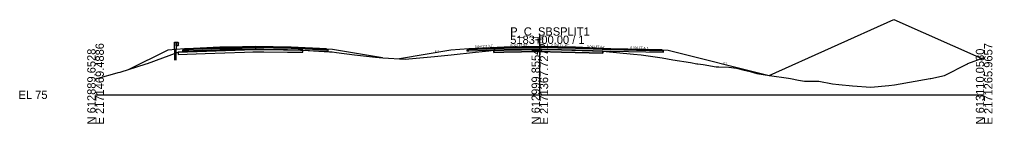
# Model space of a CAD drawing. Extents: x -26 to 1303, y -3010 to 12033.
# Drawn here: x -25.7 to 302.8, y 5990.3 to 6025.5 of the extents above; entities that cross this region are included whole.
import ezdxf

# ---------------------------------------------------------------- set-up
doc = ezdxf.new("R2010")
doc.units = 0
for name, color, linetype in [('RD_GPK_XS_Cell', 7, 'Continuous'), ('RD_PD_Final_TrvlWay', 7, 'Continuous'), ('RD_Sketch10', 7, 'Continuous'), ('RD_XS_Base', 7, 'Continuous'), ('RD_XS_ExGround', 7, 'Continuous'), ('RD_XS_ExPaveRet', 7, 'Continuous'), ('RD_XS_GR', 7, 'Continuous'), ('RD_XS_Greenside', 7, 'Continuous'), ('RD_XS_Pave', 7, 'Continuous'), ('RD_XS_PaveOvlay_CP', 7, 'Continuous'), ('RD_XS_TieSlope', 7, 'Continuous'), ('RD_XS_TX_Elev_EX', 7, 'Continuous'), ('RD_XS_TX_Elev_PR', 7, 'Continuous'), ('RD_XS_TX_Slope', 7, 'Continuous')]:
    doc.layers.add(name, color=color, linetype=linetype)

msp = doc.modelspace()

# ---------------------------------------------------------------- linework, layer by layer
at = {"layer": 'RD_GPK_XS_Cell'}
for p, q in [((150, 6000), (150, 6020)), ((0, 6000), (150, 6000)), ((150, 6000), (300, 6000))]:
    msp.add_line(p, q, dxfattribs=at)
at = {"layer": 'RD_PD_Final_TrvlWay'}
msp.add_lwpolyline([(27.17, 6011.74), (27.17, 6015.35), (26.67, 6015.31), (26.67, 6011.74)], dxfattribs=at)
at = {"layer": 'RD_Sketch10'}
msp.add_lwpolyline([(227.42, 6006.55), (269.55, 6025.46), (299.19, 6012.32)], dxfattribs=at)
at = {"layer": 'RD_XS_Base'}
for p, q in [((33.12, 6015.38), (42, 6015.73)), ((42, 6015.73), (45.12, 6015.8)), ((45.12, 6015.8), (54, 6015.97)), ((54, 6015.47), (45.12, 6015.3)), ((54, 6016.01), (54, 6016.13)), ((54, 6016.13), (54, 6015.64)), ((54, 6015.97), (54, 6016.13)), ((54, 6016.13), (54, 6015.47)), ((54, 6015.97), (54, 6016.01)), ((54, 6015.97), (54, 6015.6)), ((54, 6015.97), (54, 6015.47)), ((66, 6015.73), (54, 6015.97)), ((54, 6015.97), (54, 6015.97)), ((54, 6015.64), (54, 6015.47)), ((54, 6015.6), (54, 6015.47)), ((54, 6015.47), (54, 6015.47)), ((54, 6015.47), (54, 6015.47)), ((54, 6015.47), (66, 6015.23)), ((78, 6015.25), (66, 6015.73)), ((68, 6015.65), (68, 6015.65)), ((126, 6015.26), (138, 6015.74)), ((138, 6015.74), (150, 6015.98)), ((150, 6015.48), (138, 6015.24)), ((150, 6015.98), (150, 6016.14)), ((150, 6016.14), (150, 6015.48)), ((150, 6015.98), (150, 6015.98)), ((162, 6015.74), (150, 6015.98)), ((150, 6015.98), (150, 6015.98)), ((150, 6015.98), (150, 6015.48)), ((150, 6015.48), (150, 6015.48)), ((150, 6015.48), (162, 6015.24)), ((150, 6015.48), (150, 6015.48)), ((174, 6015.26), (162, 6015.74)), ((162, 6015.74), (162, 6015.74)), ((29.5, 6015.23), (29.63, 6015.24)), ((29.5, 6014.86), (29.5, 6015.23)), ((29.5, 6014.73), (29.5, 6014.86)), ((29.63, 6014.74), (29.5, 6014.73)), ((29.63, 6015.24), (30, 6015.25)), ((30, 6014.75), (29.63, 6014.74)), ((30, 6015.25), (33.12, 6015.38)), ((33.12, 6014.88), (30, 6014.75)), ((42, 6015.23), (33.12, 6014.88)), ((45.12, 6015.3), (42, 6015.23)), ((66, 6015.23), (78.5, 6014.73)), ((68, 6015.15), (68, 6015.15)), ((78.5, 6015.23), (78, 6015.25)), ((78, 6015.25), (78, 6015.25)), ((78.5, 6014.73), (78.5, 6015.23)), ((78.5, 6015.23), (78.5, 6015.23)), ((78.5, 6014.73), (78.5, 6014.73)), ((78.5, 6014.73), (78.5, 6014.73)), ((125.5, 6015.24), (126, 6015.26)), ((125.5, 6014.74), (125.5, 6015.24)), ((125.5, 6015.24), (125.5, 6015.24)), ((126, 6014.76), (125.5, 6014.74)), ((125.5, 6014.74), (125.5, 6014.74)), ((125.5, 6014.74), (125.5, 6014.74)), ((126, 6015.26), (126, 6015.26)), ((138, 6015.24), (126, 6014.76)), ((126, 6014.76), (126, 6014.76)), ((162, 6015.24), (162, 6015.24)), ((162, 6015.24), (174, 6014.76)), ((191.3, 6014.92), (174, 6015.26)), ((174, 6015.26), (174, 6015.26)), ((174, 6014.76), (174, 6014.76)), ((174, 6014.76), (191.8, 6014.41)), ((191.8, 6014.91), (191.3, 6014.92)), ((191.3, 6014.92), (191.3, 6014.92)), ((191.8, 6014.41), (191.8, 6014.91)), ((191.8, 6014.91), (191.8, 6014.91)), ((191.8, 6014.41), (191.8, 6014.41)), ((191.8, 6014.41), (191.8, 6014.41))]:
    msp.add_line(p, q, dxfattribs=at)
at = {"layer": 'RD_XS_ExGround'}
msp.add_lwpolyline([(0, 6005.43), (0.84, 6005.69), (7.25, 6007.44), (7.67, 6007.53), (8.33, 6007.71), (17.14, 6010.43), (17.59, 6010.61), (22.72, 6012.45), (27.85, 6014.42), (50.25, 6015.17), (54.03, 6015.3), (56.79, 6015.27), (70.03, 6015.13), (79.03, 6014.55), (79.85, 6014.51), (81.31, 6014.33), (87.43, 6013.5), (94.52, 6012.73), (97.02, 6012.53), (104.5, 6012.1), (114.43, 6012.99), (120.1, 6013.49), (128.31, 6014.37), (131.7, 6014.75), (132.73, 6014.86), (134.48, 6015.04), (137.87, 6015.11), (149.77, 6015.35), (157.32, 6015.15), (171.23, 6014.8), (181.6, 6013.75), (184.21, 6013.5), (186.55, 6013.2), (191.34, 6012.52), (194.86, 6011.87), (200.89, 6010.87), (203.05, 6010.5), (203.39, 6010.48), (205.18, 6010.22), (209.48, 6009.49), (210.47, 6009.51), (213.76, 6009.39), (216.44, 6008.96), (218.99, 6008.34), (221.01, 6007.83), (223.23, 6007.24), (227.59, 6006.52), (233.9, 6005.6), (234.6, 6005.5), (237.37, 6004.99), (239.33, 6004.67), (239.91, 6004.57), (244.24, 6004.57), (248.78, 6003.74), (250.93, 6003.47), (255.6, 6003.04), (261.73, 6002.64), (267.79, 6003.2), (269.73, 6003.37), (281.77, 6005.5), (282.04, 6005.55), (286.67, 6006.49), (294.15, 6010.35), (294.47, 6010.5), (294.55, 6010.54), (300, 6012.63)], dxfattribs=at)
at = {"layer": 'RD_XS_ExPaveRet'}
for points in [[(56.79, 6015.27), (54.7, 6015.3), (54.03, 6015.3), (53.12, 6015.27), (50.25, 6015.17), (36.98, 6014.73), (27.85, 6014.42), (27.85, 6014.42), (27.85, 6014.42), (27.85, 6014.01), (27.85, 6013.67), (27.85, 6013.67), (27.85, 6013.67), (36.98, 6013.98), (50.25, 6014.42), (53.12, 6014.52), (54.03, 6014.55), (54.7, 6014.55), (56.79, 6014.52), (64.8, 6014.43), (70.03, 6014.38), (70.03, 6014.72), (70.03, 6015.13), (64.8, 6015.18), (56.79, 6015.27)], [(56.79, 6015.27), (54.7, 6015.3), (54.03, 6015.3), (53.12, 6015.27), (50.25, 6015.17), (36.98, 6014.73), (27.85, 6014.42), (27.85, 6014.42), (27.85, 6014.42), (27.85, 6014.01), (27.85, 6013.67), (27.85, 6013.67), (27.85, 6013.67), (36.98, 6013.98), (50.25, 6014.42), (53.12, 6014.52), (54.03, 6014.55), (54.7, 6014.55), (56.79, 6014.52), (64.8, 6014.43), (70.03, 6014.38), (70.03, 6014.72), (70.03, 6015.13), (64.8, 6015.18), (56.79, 6015.27)], [(171.23, 6014.8), (171.23, 6014.8), (171.23, 6014.05), (171.23, 6014.05), (157.32, 6014.4), (157.32, 6014.4), (149.77, 6014.6), (149.77, 6014.6), (137.87, 6014.36), (137.87, 6014.36), (134.48, 6014.29), (134.48, 6014.29), (134.48, 6015.04), (134.48, 6015.04), (134.48, 6015.04), (137.87, 6015.11), (137.87, 6015.11), (149.77, 6015.35), (149.77, 6015.35), (157.32, 6015.15), (157.32, 6015.15), (171.23, 6014.8), (171.23, 6014.8)], [(157.32, 6015.15), (149.77, 6015.35), (137.87, 6015.11), (134.48, 6015.04), (134.48, 6014.29), (137.87, 6014.36), (149.77, 6014.6), (157.32, 6014.4), (171.23, 6014.05), (171.23, 6014.8), (157.32, 6015.15)]]:
    msp.add_lwpolyline(points, dxfattribs=at)
at = {"layer": 'RD_XS_GR'}
for p, q in [((26.67, 6015.31), (26.67, 6017.74)), ((26.67, 6017.74), (26.92, 6017.74)), ((26.92, 6017.74), (27.17, 6017.74)), ((27.17, 6017.74), (27.17, 6015.35)), ((27.17, 6016.57), (27.17, 6017.74)), ((27.17, 6017.74), (27.83, 6017.74)), ((27.83, 6016.57), (27.17, 6016.57)), ((27.83, 6017.74), (27.83, 6016.57)), ((28.03, 6017.52), (27.83, 6017.74)), ((27.83, 6017.74), (27.83, 6016.88)), ((27.83, 6017.16), (27.9, 6017.23)), ((28.03, 6016.94), (27.83, 6017.16)), ((27.83, 6016.88), (27.83, 6016.57)), ((27.83, 6016.57), (27.9, 6016.65)), ((27.9, 6017.23), (28.1, 6017.45)), ((27.9, 6016.65), (28.1, 6016.86)), ((28.1, 6017.45), (28.03, 6017.52)), ((28.1, 6016.86), (28.03, 6016.94)), ((27.17, 6015.35), (26.67, 6015.31))]:
    msp.add_line(p, q, dxfattribs=at)
at = {"layer": 'RD_XS_Greenside'}
for p, q in [((24.35, 6015.12), (11.04, 6008.46)), ((80, 6015.41), (96.83, 6012.61)), ((120, 6015.1), (102.63, 6012.21)), ((193.3, 6015.08), (227.42, 6006.55))]:
    msp.add_line(p, q, dxfattribs=at)
at = {"layer": 'RD_XS_Pave'}
for p, q in [((33.12, 6015.7), (30, 6015.57)), ((30, 6015.57), (30, 6015.45)), ((33.12, 6015.54), (30, 6015.41)), ((30, 6015.41), (33.12, 6015.54)), ((30, 6015.45), (30, 6015.41)), ((42, 6016.05), (33.12, 6015.7)), ((42, 6015.89), (33.12, 6015.54)), ((33.12, 6015.54), (42, 6015.89)), ((33.12, 6015.38), (42, 6015.73)), ((45.12, 6016.11), (42, 6016.05)), ((45.12, 6015.95), (42, 6015.89)), ((42, 6015.89), (45.12, 6015.95)), ((42, 6015.73), (45.12, 6015.8)), ((54, 6016.29), (45.12, 6016.11)), ((54, 6016.13), (45.12, 6015.95)), ((45.12, 6015.95), (54, 6016.13)), ((45.12, 6015.8), (54, 6015.97)), ((66, 6016.05), (54, 6016.29)), ((54, 6016.01), (54, 6016.13)), ((54, 6016.13), (54, 6016.01)), ((54, 6015.97), (54, 6016.13)), ((54, 6016.13), (66, 6015.89)), ((66, 6015.89), (54, 6016.13)), ((54, 6016.13), (54, 6015.97)), ((54, 6015.97), (54, 6016.01)), ((54, 6016.01), (54, 6015.97)), ((54, 6015.97), (54, 6015.97)), ((54, 6015.97), (54, 6015.97)), ((54, 6015.97), (66, 6015.73)), ((78, 6015.57), (66, 6016.05)), ((66, 6015.89), (78, 6015.41)), ((78, 6015.41), (66, 6015.89)), ((66, 6015.73), (78, 6015.25)), ((68, 6015.97), (68, 6015.97)), ((68, 6015.81), (68, 6015.81)), ((68, 6015.81), (68, 6015.81)), ((68, 6015.65), (68, 6015.65)), ((78, 6015.41), (78, 6015.57)), ((78, 6015.57), (78, 6015.57)), ((138, 6016.06), (126, 6015.58)), ((138, 6015.9), (126, 6015.42)), ((126, 6015.42), (138, 6015.9)), ((126, 6015.26), (138, 6015.74)), ((126, 6015.58), (126, 6015.58)), ((126, 6015.58), (126, 6015.42)), ((150, 6016.3), (138, 6016.06)), ((150, 6016.14), (138, 6015.9)), ((138, 6015.9), (150, 6016.14)), ((138, 6015.74), (150, 6015.98)), ((162, 6016.06), (150, 6016.3)), ((150, 6015.98), (150, 6016.14)), ((150, 6016.14), (162, 6015.9)), ((162, 6015.9), (150, 6016.14)), ((150, 6016.14), (150, 6016.14)), ((150, 6016.14), (150, 6015.98)), ((150, 6015.98), (150, 6015.98)), ((150, 6015.98), (150, 6015.98)), ((150, 6015.98), (150, 6015.98)), ((150, 6015.98), (162, 6015.74)), ((174, 6015.58), (162, 6016.06)), ((162, 6016.06), (162, 6016.06)), ((162, 6015.9), (162, 6015.9)), ((162, 6015.9), (174, 6015.42)), ((174, 6015.42), (162, 6015.9)), ((162, 6015.9), (162, 6015.9)), ((162, 6015.74), (162, 6015.74)), ((162, 6015.74), (174, 6015.26)), ((191.3, 6015.24), (174, 6015.58)), ((174, 6015.58), (174, 6015.58)), ((30, 6015.41), (30, 6015.3)), ((30, 6015.25), (33.12, 6015.38)), ((30, 6015.3), (30, 6015.25)), ((78, 6015.41), (78, 6015.41)), ((78, 6015.41), (78, 6015.41)), ((78, 6015.25), (78, 6015.41)), ((78, 6015.41), (78, 6015.41)), ((78, 6015.25), (78, 6015.25)), ((78, 6015.25), (78, 6015.25)), ((126, 6015.42), (126, 6015.42)), ((126, 6015.42), (126, 6015.26)), ((126, 6015.42), (126, 6015.42)), ((126, 6015.42), (126, 6015.42)), ((126, 6015.26), (126, 6015.26)), ((126, 6015.26), (126, 6015.26)), ((174, 6015.42), (174, 6015.42)), ((174, 6015.42), (191.3, 6015.08)), ((191.3, 6015.08), (174, 6015.42)), ((174, 6015.42), (174, 6015.42)), ((174, 6015.26), (174, 6015.26)), ((174, 6015.26), (191.3, 6014.92)), ((191.3, 6015.08), (191.3, 6015.24)), ((191.3, 6015.24), (191.3, 6015.24)), ((191.3, 6015.08), (191.3, 6015.08)), ((191.3, 6015.08), (191.3, 6015.08)), ((191.3, 6014.92), (191.3, 6015.08)), ((191.3, 6015.08), (191.3, 6015.08)), ((191.3, 6014.92), (191.3, 6014.92)), ((191.3, 6014.92), (191.3, 6014.92))]:
    msp.add_line(p, q, dxfattribs=at)
at = {"layer": 'RD_XS_PaveOvlay_CP'}
for p, q in [((30, 6015.57), (42, 6016.05)), ((42, 6016.05), (54, 6016.29)), ((54, 6016.29), (66, 6016.05)), ((66, 6016.05), (78, 6015.57)), ((138, 6016.06), (126, 6015.58)), ((126, 6015.58), (126, 6015.58)), ((150, 6016.3), (138, 6016.06)), ((162, 6016.06), (150, 6016.3)), ((174, 6015.58), (162, 6016.06)), ((162, 6016.06), (162, 6016.06)), ((191.3, 6015.24), (174, 6015.58)), ((174, 6015.58), (174, 6015.58)), ((191.3, 6015.24), (191.3, 6015.24))]:
    msp.add_line(p, q, dxfattribs=at)
at = {"layer": 'RD_XS_TieSlope'}
for p, q in [((30, 6015.57), (24.35, 6015.12)), ((78, 6015.57), (80, 6015.41)), ((126, 6015.58), (120, 6015.1)), ((191.3, 6015.24), (193.3, 6015.08))]:
    msp.add_line(p, q, dxfattribs=at)

# ---------------------------------------------------------------- texts
at = {"layer": 'RD_GPK_XS_Cell'}
for s, p in [('P_C_SBSPLIT1', (140, 6020)), ('5183+00.00 / 1', (140, 6017.2)), ('EL 75', (-26, 5998.6))]:
    msp.add_text(s, height=2.8, dxfattribs=at).set_placement(p)
for s, p in [('N 612889.6528', (0, 5990)), ('E 2171469.4886', (2.8, 5990)), ('N 612999.8554', (150, 5990)), ('E 2171367.7272', (152.8, 5990)), ('N 613110.0580', (300, 5990)), ('E 2171265.9657', (302.8, 5990))]:
    msp.add_text(s, height=2.8, rotation=90, dxfattribs=at).set_placement(p)
at = {"layer": 'RD_XS_TX_Elev_EX'}
msp.add_text('90.34', height=0.6, rotation=90, dxfattribs=at).set_placement((149.72, 6016.84))
at = {"layer": 'RD_XS_TX_Elev_PR'}
msp.add_text('91.30', height=1, rotation=90, dxfattribs=at).set_placement((151.2, 6016.48))
at = {"layer": 'RD_XS_TX_Slope'}
for s, rotation, p in [('0.040 FT./FT.', 2.2906, (128.1, 6015.92)), ('0.020 FT./FT.', 1.1458, (139.97, 6016.33)), ('0.020 FT./FT.', 358.8542, (153.94, 6016.32)), ('0.040 FT./FT.', 357.7094, (165.94, 6016)), ('0.020 FT./FT.', 358.8542, (180.59, 6015.55)), ('6:1', 9.4623, (114.62, 6014.26)), ('4:1', 345.9638, (211.76, 6010.52))]:
    msp.add_text(s, height=0.75, rotation=rotation, dxfattribs=at).set_placement(p)

doc.saveas('drawing.dxf')
